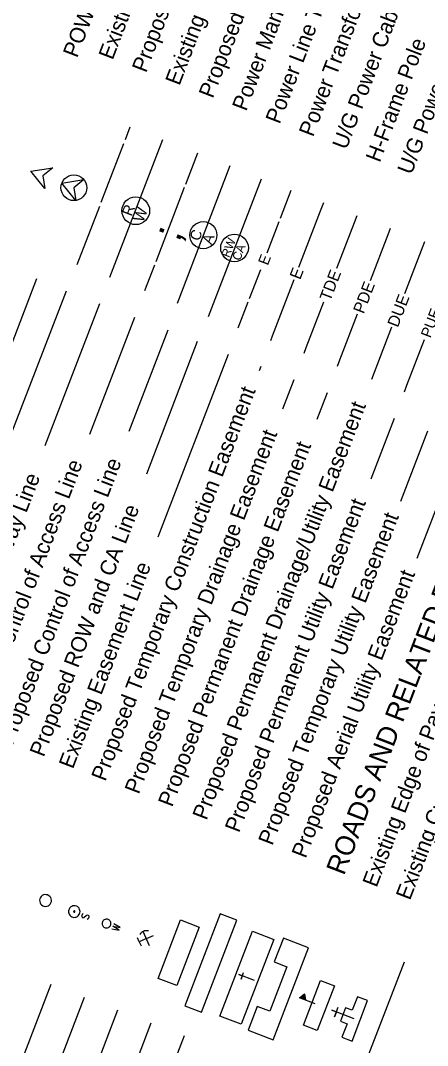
# Model space of a CAD drawing. Extents: x 1015221 to 1064345, y 619216 to 647967.
# Drawn here: x 1048770 to 1050556, y 626042 to 630539 of the extents above; entities that cross this region are included whole.
import ezdxf

# ---------------------------------------------------------------- set-up
doc = ezdxf.new("R2010")
doc.units = 0
doc.layers.add('Default', color=7, linetype='Continuous')

msp = doc.modelspace()

# ---------------------------------------------------------------- linework, layer by layer
at = {"layer": 'Default'}
for p, q in [((1049230.3, 630017.4), (1049251.5, 630072.3)), ((1049124.8, 629742.7), (1049223.3, 629999.1)), ((1049162.5, 629413.1), (1049394.6, 630017.3)), ((1049496, 629821.8), (1049548.4, 629958.2)), ((1049458.7, 629299.3), (1049690.8, 629903.5)), ((1048816.2, 629877.8), (1048912.9, 629893.2)), ((1048877.7, 629801.7), (1048816.2, 629877.8)), ((1048912.9, 629893.2), (1048868.9, 629857.6)), ((1048868.9, 629857.6), (1048877.7, 629801.7)), ((1048951.7, 629825.8), (1049048.4, 629841.2)), ((1049013.3, 629749.6), (1048951.7, 629825.8)), ((1049048.4, 629841.2), (1049004.5, 629805.5)), ((1049004.5, 629805.5), (1049013.3, 629749.6)), ((1049365.4, 629481.9), (1049490.4, 629807.2)), ((1049595.1, 629240.8), (1049827.3, 629845)), ((1049910.8, 629672.1), (1049957.9, 629794.7)), ((1049019.3, 629468.1), (1049117.8, 629724.4)), ((1050086.7, 629704.2), (1050100.4, 629740)), ((1049991.7, 629457), (1050086.7, 629704.2)), ((1050235.2, 629653.3), (1050246.9, 629683.7)), ((1049852.4, 629520.1), (1049905.2, 629657.5)), ((1050157.8, 629451.9), (1050235.2, 629653.3)), ((1050383, 629600.3), (1050393.4, 629627.4)), ((1050305.6, 629398.9), (1050383, 629600.3)), ((1050456.3, 629341), (1050544.1, 629569.5)), ((1049316.3, 629354), (1049359.8, 629467.2)), ((1049775.1, 629318.7), (1049824.3, 629446.9)), ((1048841, 629405.5), (1048724.5, 629102.4)), ((1049875.6, 629154.9), (1049970.6, 629402.1)), ((1048970, 629352.3), (1048681.5, 628601.4)), ((1049116.5, 629296), (1048877.1, 628673.1)), ((1049725.8, 629190.5), (1049769.4, 629304.1)), ((1050024.2, 629104), (1050101.6, 629305.4)), ((1049271.2, 629236.6), (1049073.5, 628722.1)), ((1050171.9, 629051), (1050249.3, 629252.4)), ((1049416.3, 629180.8), (1049245.5, 628736.1)), ((1050312, 628965.3), (1050400, 629194.5)), ((1049546.1, 629130.1), (1049322.8, 628548.8)), ((1049868.3, 629135.7), (1049875.6, 629154.9)), ((1050465.1, 628938.7), (1050542.4, 629140.1)), ((1050014.7, 629079.4), (1050024.2, 629104)), ((1049680.7, 629073.1), (1049373.2, 628272.9)), ((1050161.2, 629023.2), (1050171.9, 629051)), ((1049824.2, 629021.1), (1049817.2, 629002.7)), ((1049969.6, 628962), (1049920.4, 628833.9)), ((1050116.1, 628905.8), (1050071.1, 628788.5)), ((1050454.3, 628910.6), (1050465.1, 628938.7)), ((1050409.2, 628793.2), (1050306.7, 628526.5)), ((1050555.6, 628736.9), (1050437.1, 628428.3)), ((1050702.1, 628680.6), (1050509.5, 628179.2)), ((1049645.7, 626619.2), (1049490.9, 626216.4)), ((1049718.9, 626591.1), (1049645.7, 626619.2)), ((1049373.6, 626336.4), (1049472.1, 626592.8)), ((1049472.1, 626592.8), (1049554.1, 626561.3)), ((1049564.1, 626188.2), (1049718.9, 626591.1)), ((1049337, 626479.4), (1049308.9, 626542.5)), ((1049322.9, 626510.9), (1049354.5, 626525)), ((1049554.1, 626561.3), (1049455.6, 626305)), ((1049644.8, 626171.1), (1049787.9, 626543.7)), ((1049787.9, 626543.7), (1049881.6, 626507.6)), ((1049291.4, 626496.9), (1049299.5, 626478.6)), ((1049322.9, 626510.9), (1049319.4, 626509.3)), ((1049881.6, 626507.6), (1049738.5, 626135.1)), ((1049923.7, 626512.4), (1049883.9, 626408.7)), ((1050033.6, 626470.2), (1049923.7, 626512.4)), ((1049878.8, 626067.3), (1050033.6, 626470.2)), ((1049938.8, 626387.5), (1049863.7, 626192.2)), ((1049883.9, 626408.7), (1049938.8, 626387.5)), ((1050229.3, 625823.5), (1050454.4, 626409.5)), ((1048902.8, 626309), (1048268.5, 624657.9)), ((1049455.6, 626305), (1049373.6, 626336.4)), ((1050011.3, 626131.4), (1050086.5, 626327.1)), ((1050147.3, 626303.8), (1050072.1, 626108)), ((1050086.5, 626327.1), (1050147.3, 626303.8)), ((1049049.3, 626252.7), (1048414.9, 624601.7)), ((1050248.7, 626255.8), (1050225.9, 626196.5)), ((1050293.2, 626238.7), (1050248.7, 626255.8)), ((1049490.9, 626216.4), (1049564.1, 626188.2)), ((1049808.8, 626213.3), (1049768.9, 626109.6)), ((1049863.7, 626192.2), (1049808.8, 626213.3)), ((1050196.3, 626207.8), (1050173.5, 626148.5)), ((1050225.9, 626196.5), (1050196.3, 626207.8)), ((1050224.9, 626060.7), (1050293.2, 626238.7)), ((1049195.8, 626196.4), (1048662.7, 624809)), ((1049738.5, 626135.1), (1049644.8, 626171.1)), ((1049342.3, 626140.2), (1048809.2, 624752.8)), ((1050072.1, 626108), (1050011.3, 626131.4)), ((1050173.5, 626148.5), (1050203.1, 626137.1)), ((1050203.1, 626137.1), (1050180.3, 626077.8)), ((1049488.7, 626083.9), (1048997.8, 624806)), ((1049768.9, 626109.6), (1049878.8, 626067.3)), ((1050180.3, 626077.8), (1050224.9, 626060.7))]:
    msp.add_line(p, q, dxfattribs=at)
for points in [[(1048889.5, 626702.7), (1048883.2, 626703.6), (1048877.5, 626704.3), (1048871.7, 626702.8), (1048866.1, 626699.7), (1048861.7, 626696.2), (1048857.8, 626691.8), (1048855.5, 626685.9), (1048854, 626679.8), (1048854.6, 626673.7), (1048856, 626667.9), (1048858.7, 626663.1), (1048862.9, 626658.5), (1048868.2, 626655), (1048873.4, 626653), (1048879.8, 626652.1), (1048885.9, 626652.7), (1048891.1, 626654.4), (1048896.1, 626657.7), (1048900.7, 626661.9), (1048903.6, 626667.5), (1048905.8, 626673.3), (1048905.9, 626679.3), (1048905, 626684.8), (1048902.9, 626690.9), (1048899.6, 626695.8), (1048894.9, 626699.1), (1048889.5, 626702.7)], [(1049015.6, 626653.4), (1049010.7, 626654.8), (1049005.4, 626655.2), (1049000.2, 626654.4), (1048995.6, 626652.4), (1048991.3, 626649.7), (1048987.2, 626646.3), (1048984.6, 626642.4), (1048982.1, 626637.4), (1048981.3, 626632.2), (1048981.1, 626627.4), (1048981.8, 626622.2), (1048983.8, 626617.6), (1048987, 626613.1), (1048990.6, 626609.5), (1048995, 626606.8), (1048999.7, 626604.9), (1049004.8, 626604.1), (1049009.9, 626604.3), (1049015.2, 626605.5), (1049019.8, 626607.6), (1049023.9, 626611), (1049026.9, 626614.7), (1049029.7, 626619.1), (1049031.3, 626624.5), (1049031.9, 626629.1), (1049031.2, 626634.3), (1049029.8, 626639.2), (1049027.8, 626643.9), (1049024.4, 626647.9), (1049020.2, 626651.1), (1049015.6, 626653.4)], [(1049004, 626631.7), (1049003.4, 626630.3), (1049003.8, 626628.5), (1049004.9, 626627), (1049006.5, 626626.9), (1049008.3, 626627.3), (1049009.3, 626628.5), (1049009.4, 626630.2), (1049008.8, 626631.5), (1049007.1, 626632.7), (1049005.5, 626632.8), (1049004, 626631.7)], [(1049045.3, 626621.1), (1049041.4, 626617.3), (1049039.4, 626612), (1049039.6, 626606.4), (1049042.5, 626602.9), (1049043.9, 626602.3), (1049048.2, 626603.3), (1049060.3, 626614), (1049064.4, 626615.1), (1049067.1, 626613.8), (1049070, 626610.3), (1049070.6, 626605.6), (1049068.4, 626600.1), (1049066.5, 626597.9), (1049062.6, 626595.2)], [(1049154.7, 626595), (1049151.3, 626595.6), (1049147.9, 626596.3), (1049144.4, 626595.9), (1049141.1, 626594.9), (1049137.9, 626593.5), (1049135.1, 626591.6), (1049132.8, 626588.8), (1049130.7, 626586), (1049129.5, 626582.8), (1049128.5, 626579.5), (1049128.5, 626575.9), (1049128.9, 626572.8), (1049129.9, 626569.4), (1049131.4, 626566.2), (1049133.7, 626563.6), (1049136.1, 626561.4), (1049139.1, 626559.6), (1049142.5, 626558.3), (1049145.9, 626557.6), (1049149.3, 626557.7), (1049152.7, 626558), (1049155.9, 626559.4), (1049158.9, 626561.3), (1049161.3, 626563.3), (1049163.7, 626566), (1049165.2, 626569.1), (1049166.4, 626572.3), (1049166.8, 626575.7), (1049166.9, 626579.4), (1049166.1, 626582.6), (1049164.7, 626585.8), (1049162.9, 626588.8), (1049160.6, 626591.4), (1049157.6, 626593.2), (1049154.7, 626595)], [(1049171.4, 626554.2), (1049202.5, 626547.5), (1049175.5, 626564.8), (1049207.1, 626559.5), (1049179.8, 626575.9)], [(1049331.2, 626544.5), (1049325.6, 626545.3), (1049320.1, 626545.3), (1049314.7, 626544.5), (1049309.8, 626542.6), (1049304.7, 626540.3), (1049300.4, 626536.9), (1049296.4, 626532.9), (1049293.4, 626528.6)], [(1049322.9, 626510.9), (1049291.4, 626496.9), (1049283.5, 626514.7)], [(1049797.5, 626326.4), (1049728.8, 626352.7), (1049743.4, 626347.1), (1049737.8, 626332.5), (1049749.1, 626361.7)], [(1050062.7, 626224.3), (1049994, 626250.7), (1050016.3, 626268.4), (1050021, 626240.3), (1050019.4, 626242.5), (1049996.4, 626251.3), (1050015.6, 626265.6), (1050019.1, 626244.1), (1049999.2, 626252.1), (1050014.7, 626263.5), (1050017.3, 626246.7), (1050002.1, 626252.5), (1050013.8, 626261), (1050015.5, 626249.2), (1050005.2, 626253.2), (1050012.6, 626258.7), (1050013.8, 626251.4), (1050008.2, 626253.6), (1050011.8, 626256.5), (1050012.2, 626253.6), (1050010.5, 626253.9), (1050011, 626254.7)], [(1050234.3, 626159.2), (1050135.5, 626197.2), (1050156.5, 626189.1), (1050148.4, 626168), (1050164.6, 626210.1)]]:
    msp.add_lwpolyline(points, dxfattribs=at)
for centre, radius in [((1049004.5, 629805.5), 56.5), ((1049276.1, 629704.4), 60.8), ((1049572.3, 629597.3), 59.5), ((1049709.3, 629541.4), 60.6)]:
    msp.add_circle(centre, radius, dxfattribs=at)

# ---------------------------------------------------------------- texts
for s, height, p in [('U/G Power Line Test Hole (SUE - LOS A)*', 68.654, (1050485.4, 629859.5)), ('Existing Power Pole', 68.654, (1049174.5, 630362.9)), ('Proposed Power Pole', 68.654, (1049321, 630306.6)), ('Existing Joint Use Pole', 68.654, (1049467.4, 630250.4)), ('Proposed Joint Use Pole', 68.654, (1049614, 630194.2)), ('U/G Power Cable Hand Hole', 68.654, (1050200, 629969.1)), ('Power Manhole', 68.654, (1049760.5, 630137.9)), ('Power Line Tower', 68.654, (1049906.9, 630081.6)), ('Power Transformer', 68.654, (1050053.3, 630025.3)), ('POWER:', 68.65, (1049018.4, 630372.1)), ('H-Frame Pole', 68.654, (1050346.4, 629912.8)), ('R', 47.7, (1049258, 629677.2)), ('W', 47.7, (1049308, 629650.7)), (';', 129.5, (1049465.7, 629563.8)), ('C', 46.6, (1049553.7, 629568.4)), ('A', 46.6, (1049607.9, 629553.5)), ('RW', 37.96, (1049685.6, 629496.3)), ('CA', 37.96, (1049733.2, 629482.7)), ('E', 47.1, (1049855.3, 629461.9)), ('E', 51.4, (1049997.2, 629399)), ('TDE', 51.39, (1050128.9, 629304.2)), ('PDE', 51.39, (1050275.9, 629249.4)), ('DUE', 51.39, (1050425.9, 629189.6)), ('PUE', 47.08, (1050568.9, 629143.4)), ('Proposed Temporary Construction Easement', 68.654, (1049142.6, 627197.4)), ('Proposed Permanent Drainage/Utility Easement', 68.654, (1049586.3, 627026.9)), ('Proposed Temporary Drainage Easement', 68.654, (1049289, 627141.1)), ('Proposed Permanent Drainage Easement', 68.654, (1049435.5, 627084.8)), ('Existing Control of Access Line', 68.654, (1048590.6, 627415.6)), ('Proposed Control of Access Line', 68.654, (1048735.4, 627355.4)), ('ROADS AND RELATED FEATURES:', 86.308, (1050189.5, 626784.5)), ('Proposed Right of Way Line', 68.654, (1048448, 627470.4)), ('Proposed ROW and CA Line', 68.654, (1048872.2, 627304.3)), ('Proposed Permanent Utility Easement', 68.654, (1049728.6, 626972.2)), ('Proposed Temporary Utility Easement', 68.654, (1049875, 626916)), ('Existing Easement Line', 68.654, (1049000.1, 627252.1)), ('Proposed Aerial Utility Easement', 68.654, (1050021.5, 626859.7)), ('Existing Edge of Pavement', 68.654, (1050332.4, 626732.2)), ('Existing Curb', 68.654, (1050478.9, 626675.9))]:
    msp.add_text(s, height=height, rotation=68.983, dxfattribs=at).set_placement(p)

doc.saveas('drawing.dxf')
